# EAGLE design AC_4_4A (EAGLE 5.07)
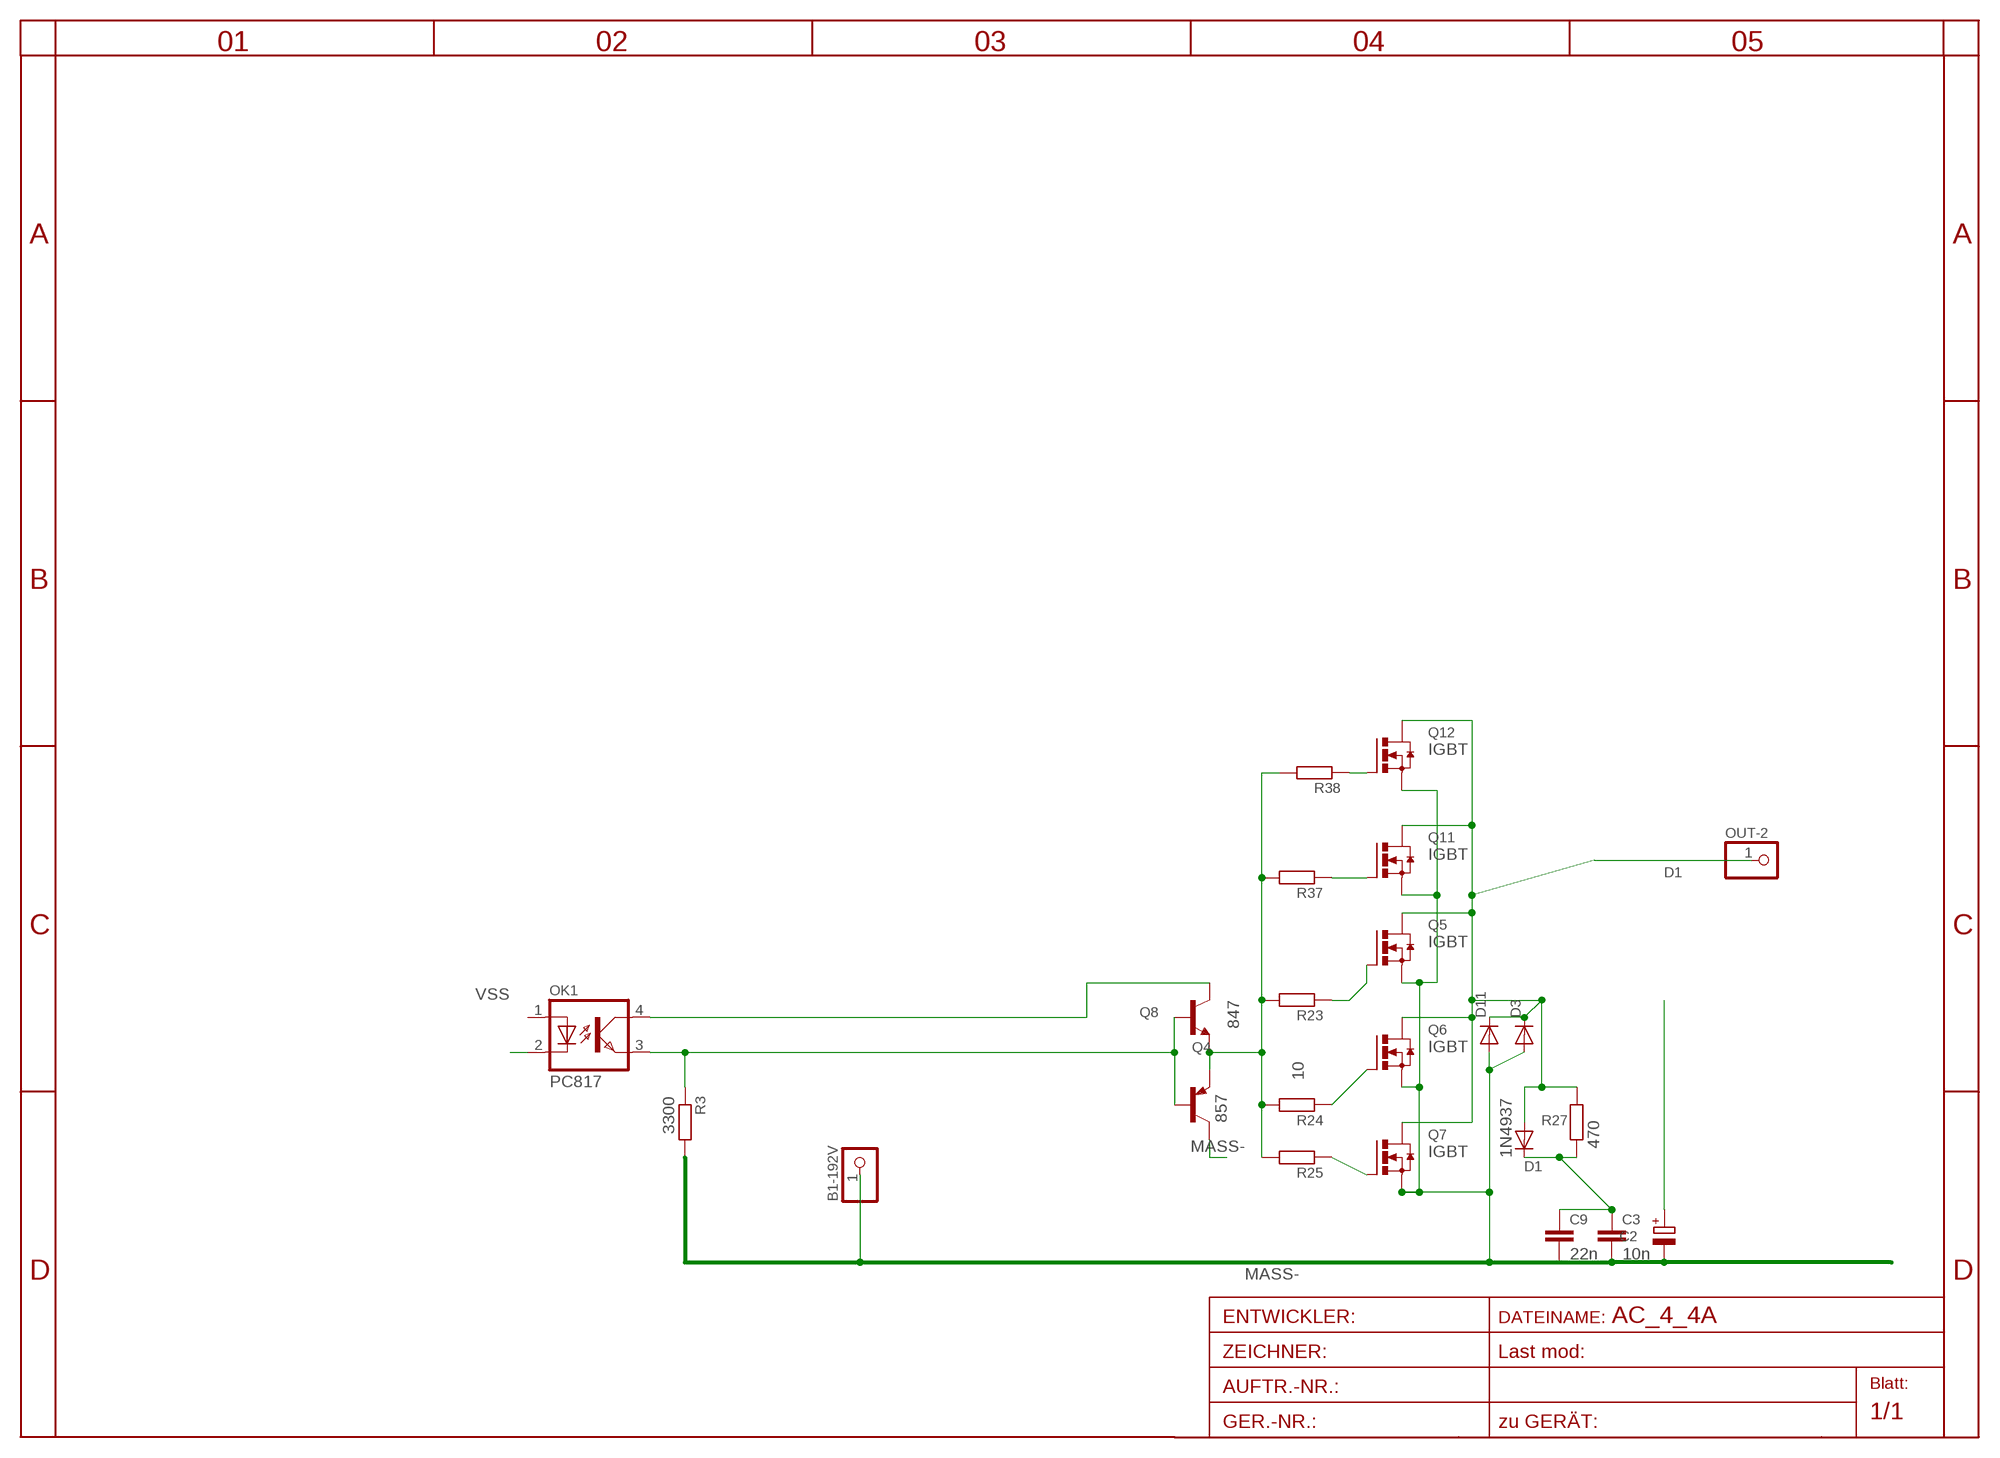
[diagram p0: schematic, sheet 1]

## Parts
B1-192V  PINHD-1X13MM2  [1X3MM2]
C2  CPOL-EUE2.5-5  [E2,5-5]
C3  10n  C-EU025_050-050X075  [C025_050-050X075]
C9  22n  C-EU102-043X133  [C102-043X133]
D1  1N4937  1N4004DO41-10  [DO41-10]
D3  DIODE-SMC  [SMC]
D11  DIODE-SMC  [SMC]
OK1  PC817  [DIL04]
OUT-2  PINHD-1X13MM2  [1X3MM2]
Q4  857  BC857ALT1SMD  [SOT23-BEC]
Q5  IGBT  N-HEXFET_DPAK-  [TO252]
Q6  IGBT  N-HEXFET_DPAK-  [TO252]
Q7  IGBT  N-HEXFET_DPAK-  [TO252]
Q8  847  BC846ALT1SMD  [SOT23]
Q11  IGBT  N-HEXFET_DPAK-  [TO252]
Q12  IGBT  N-HEXFET_DPAK-  [TO252]
R3  3300  R-EU_R0805  [R0805]
R23  R-EU_0207/12  [0207/12]
R24  R-EU_0207/12  [0207/12]
R25  10  R-EU_0207/12  [0207/12]
R27  470  R-EU_0207/10  [0207/10]
R37  R-EU_0207/12  [0207/12]
R38  R-EU_0207/12  [0207/12]

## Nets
D1: D1.A D3.C D11.C OUT-2.1 Q5.3(D) Q6.3(D) Q7.3(D) Q11.3(D) Q12.3(D) R27.2
EGATE: Q4.E Q8.2(E) R23.2 R24.2 R25.2 R37.2 R38.2
MASS-: B1-192V.1 C2.- C3.3 C9.2 D3.A D11.A Q4.C Q5.2(S) Q6.2(S) Q7.2(S) Q11.2(S) Q12.2(S) R3.2
N$2: C3.1 C9.1 D1.C R27.1
N$25: Q12.1(G) R38.1
N$26: Q6.1(G) R24.1
N$27: Q5.1(G) R23.1
N$46: Q11.1(G) R37.1
N$47: Q7.1(G) R25.1
PP1: OK1.3(EMIT) Q4.B Q8.1(B) R3.1
V_OK: C2.+ OK1.4(COL) Q8.3(C)
VSS: OK1.2(C)
Unconnected: OK1.1(A)

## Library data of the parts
B1-192V OUT-2 = pinhead:PINHD-1X1: PIN HEADER
C2 = rcl-2:CPOL-EU: POLARIZED CAPACITOR, European symbol
C3 C9 = rcl-2:C-EU: CAPACITOR, European symbol
D1 = diode:1N4004: DIODE
D3 D11 = diode:DIODE-: DIODE
OK1 = optocoupler:PC817: SHARP OPTO COUPLER
Q4 = transistor-pnp:BC857*: PNP Transistror
Q5-Q7 Q11 Q12 = transistor-power:N-HEXFET_?-*: HEXFET® Power MOSFET
Q8 = transistor-npn:BC846*: NPN Transistor
R3 R23-R25 R27 R37 R38 = rcl-2:R-EU_: RESISTOR, European symbol

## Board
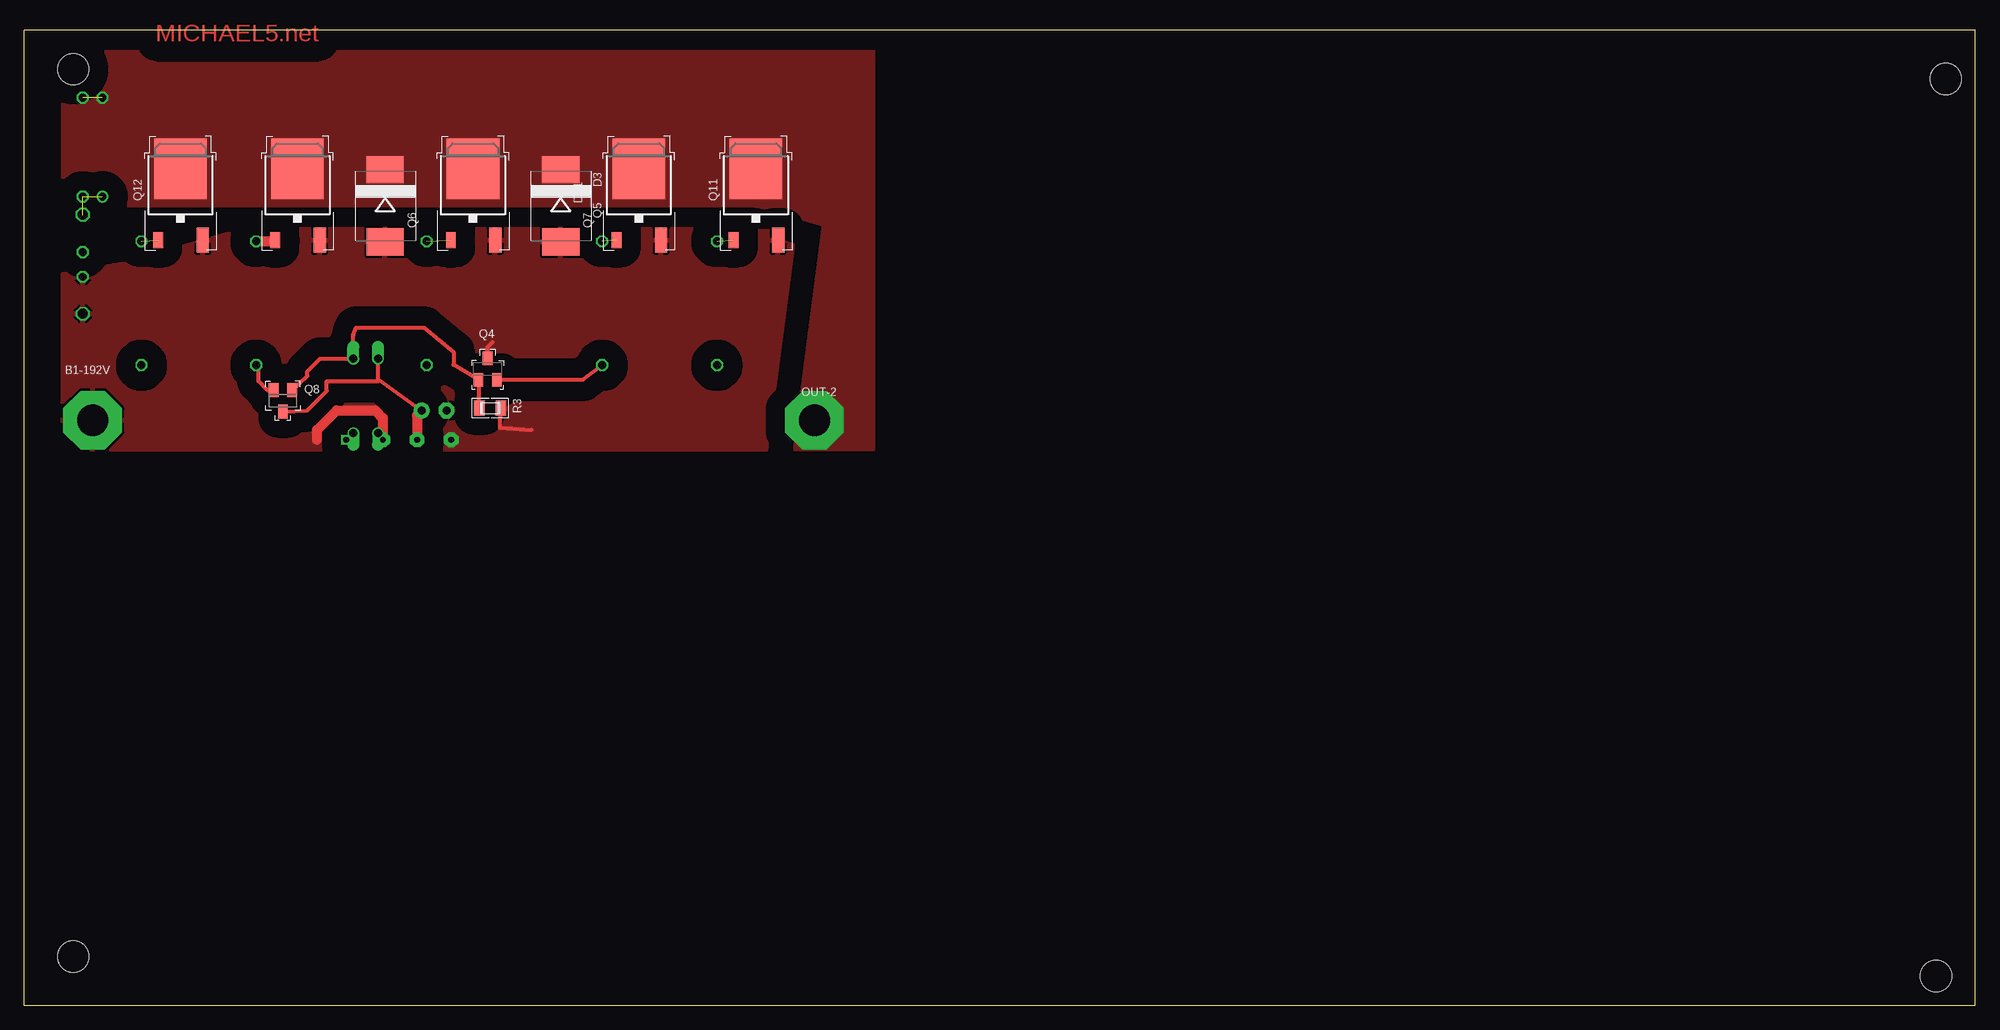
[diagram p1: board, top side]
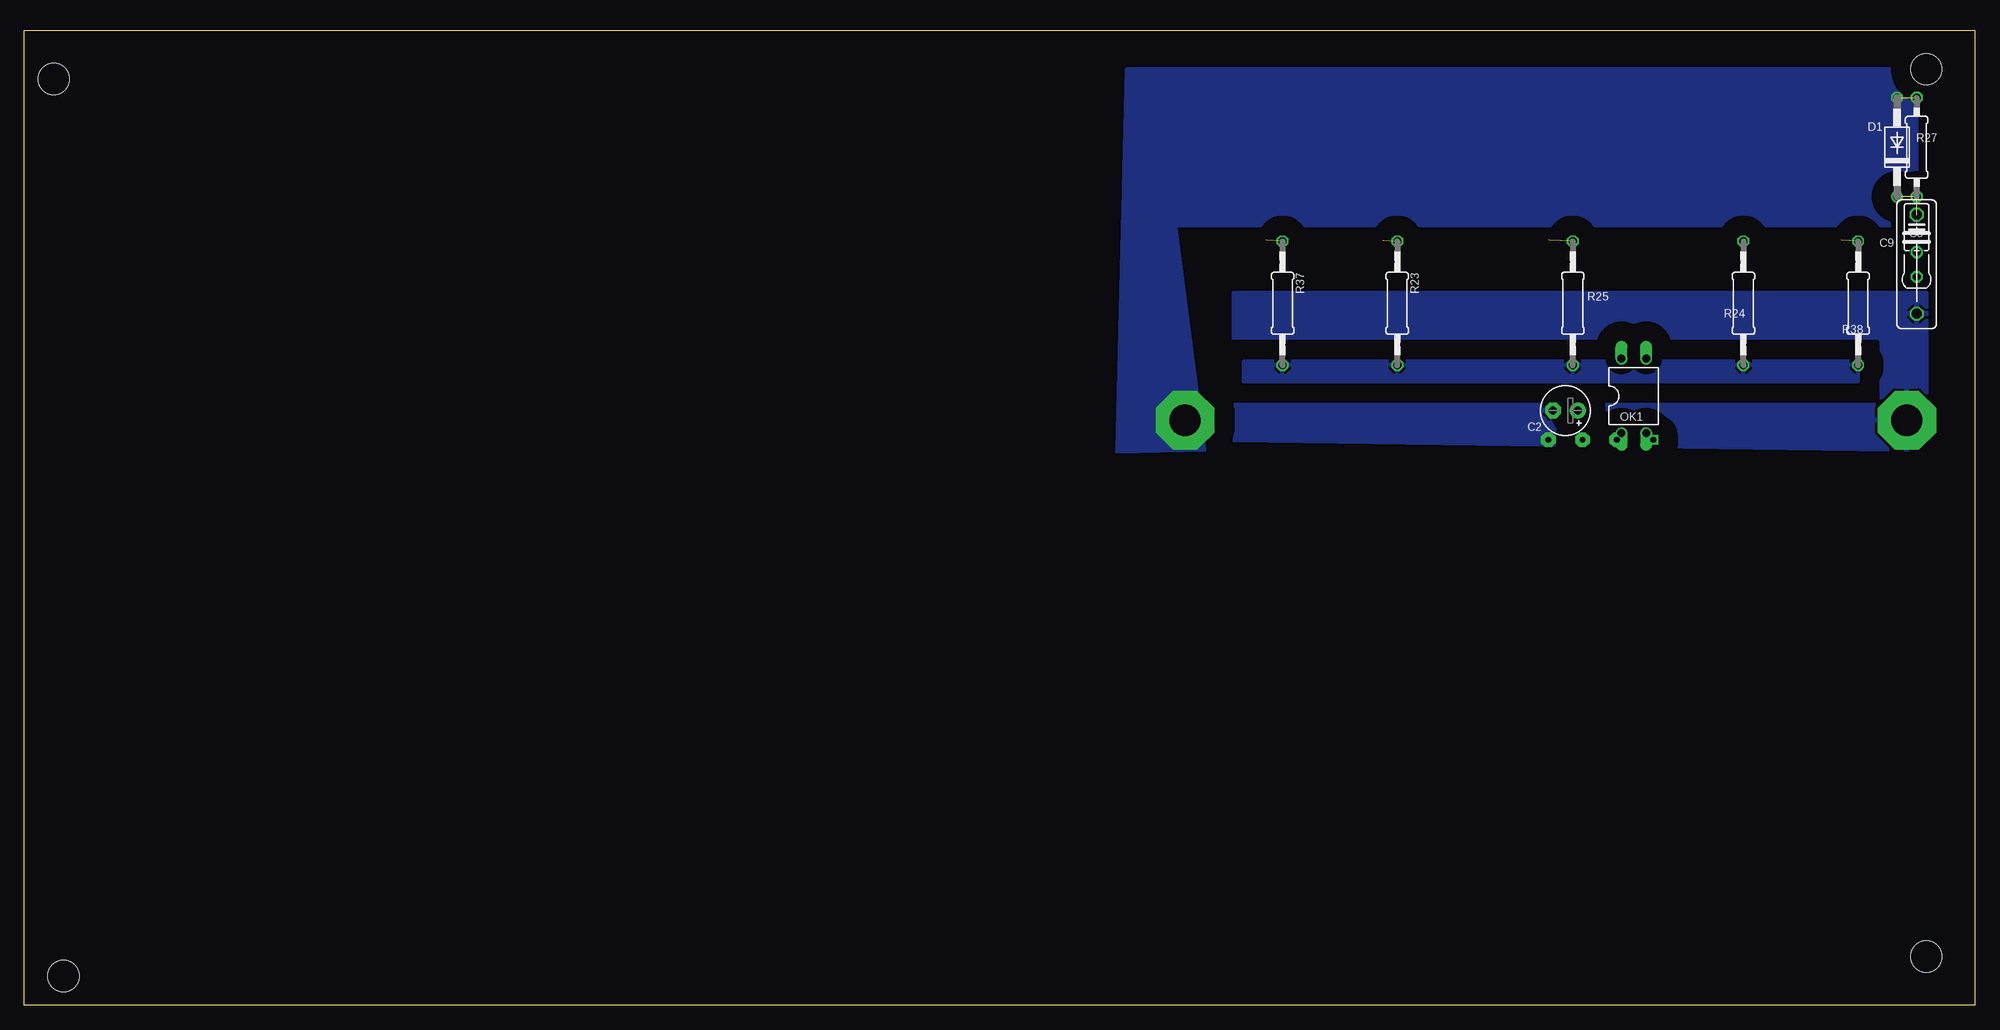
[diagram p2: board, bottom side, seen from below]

Size 200 x 100 mm. Coordinates in mm from the lower left corner, seen from the top.
Outline: 0,0 200,0 200,100 0,100 0,0
Copper layers (1*16): Top 0.035mm / dielectric 1.5mm / Bottom 0.035mm
Design rules "default *": minimum track width 12mil, minimum drill 24mil, track to track 8mil, track to pad 8mil, pad to pad 8mil, via to via 8mil, smd to smd 8mil, copper to edge 40mil, drill to drill 8mil, minimum pad ring 8mil, minimum via ring 8mil, stop-mask expansion 4mil, vias tented up to drill 0mil, thermal gap 10mil
Holes 3.2 mm at 5,96 5,5 197,95 196,3

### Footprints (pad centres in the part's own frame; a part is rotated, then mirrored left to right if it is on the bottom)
1X3MM2 = drill 3.2 pad 6 octagon: 1 0,0
E2,5-5 = drill 0.813 pad 1.6 round: + -1.27,0 | drill 0.813 pad 1.6 octagon: - 1.27,0
C025_050-050X075 = drill 0.813 octagon: 1 -3.81,0; 2 0,0; 3 2.54,0
C102-043X133 = drill 1.016 octagon: 1 -5.08,0; 2 5.08,0
DO41-10 = drill 0.8 octagon: A 5.08,0 | drill 0.8 round: C -5.08,0
SMC = smd 2.8 x 3.8: A 3.7,0; C -3.7,0
DIL04 = drill 0.813 offset: 1 -1.27,-3.81; 2 1.27,-3.81; 3 1.27,3.81; 4 -1.27,3.81
SOT23-BEC = smd 1 x 1.4: B -0.95,-1.1; C 0,1.1; E 0.95,-1.1
TO252 = smd 1 x 1.6: 1 -2.28,-3.53 | smd 1.27 x 2.54: 2 2.28,-3.53 | smd 5.4 x 6.2: 3 0,3.77
SOT23 = smd 1 x 1.4: 1 -0.95,-1.1; 2 0.95,-1.1; 3 0,1.1
R0805 = smd 1.1 x 1.5: 1 -1.1,0; 2 1.1,0
0207/12 = drill 0.813 octagon: 1 -6.35,0; 2 6.35,0
0207/10 = drill 0.813 octagon: 1 -5.08,0; 2 5.08,0

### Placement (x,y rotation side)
B1-192V  7,60 0 top
C2  42,61 180 bottom
C3  6,77.25 270 bottom
C9  6,76 270 bottom
D1  8,88 90 bottom
D3  55,82 270 top
D11  37,82 270 top
OK1  35,62.5 0 bottom
OUT-2  81,60 0 top
Q4  47.5,65.25 0 top
Q5  63,82 0 top
Q6  28,82 0 top
Q7  46,82 0 top
Q8  26.5,62 180 top
Q11  75,82 0 top
Q12  16,82 0 top
R3  47.75,61.25 0 top
R23  59.25,72 270 bottom
R24  23.75,72 270 bottom
R25  41.25,72 270 bottom
R27  6,88 90 bottom
R37  71,72 270 bottom
R38  12,72 270 bottom

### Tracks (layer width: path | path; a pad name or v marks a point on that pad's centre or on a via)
D1  (1 unrouted)
  pour Top (isolate 2, rank 2, no thermals): 4,98 87,98 87,57 79,57 82,80 75,82 4,82
  pour Bottom (isolate 2, rank 2, no thermals): 6,96 87,96 88,56.82 79,57 82,80 6,80
EGATE
  Top 0.406: Q8.2 24.9,63.1 24,64 24,65.4 R24.2 | Q4.E 57.25,64.15 R23.2
  pour Bottom (isolate 1): 12,66 75,66 75,64 12,64
MASS-  (via drill 0.6 pad 1.5)
  Top 0.406: R3.2 48.75,59.25 52,59 | Q4.C 47.5,67.5 48,68
  Top 1: v36.75,58 36.75,60.25 36,61 32,61 30,59 30,58
  other vias: 43.75,58
  pour Top (isolate 2, rank 3): 4,75 10,76 24,80 79,80 76,57 4,57
  pour Bottom (isolate 2, rank 3): 5,73 76,73 76,58 5,57
N$1  (via drill 0.6)
  other vias: 33,58
N$2  (3 unrouted)
N$25  (1 unrouted)
N$26
  Top 1: R24.1 25.6,78.35 Q6.1
N$27  (1 unrouted)
N$46  (1 unrouted)
N$47  (1 unrouted)
PP1
  Top 0.406: Q8.1 29,64.55 29,65 30.31,66.31 OK1.3 33.73,68.73 34,69.5 41,69.5 44,67 44,65.7 Q4.B 46.55,61.35 R3.1
V_OK  (via drill 0.6 pad 1.5)
  Top 0.406: 36.27,64.21 OK1.4 | 36.27,64.21 36.27,64 31,64 31,63 29,61 Q8.3 | 36.27,64.21 C2.+
  Top 1: v40.25,58 40.25,60.52 C2.+

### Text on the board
Top: MICHAEL5.net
